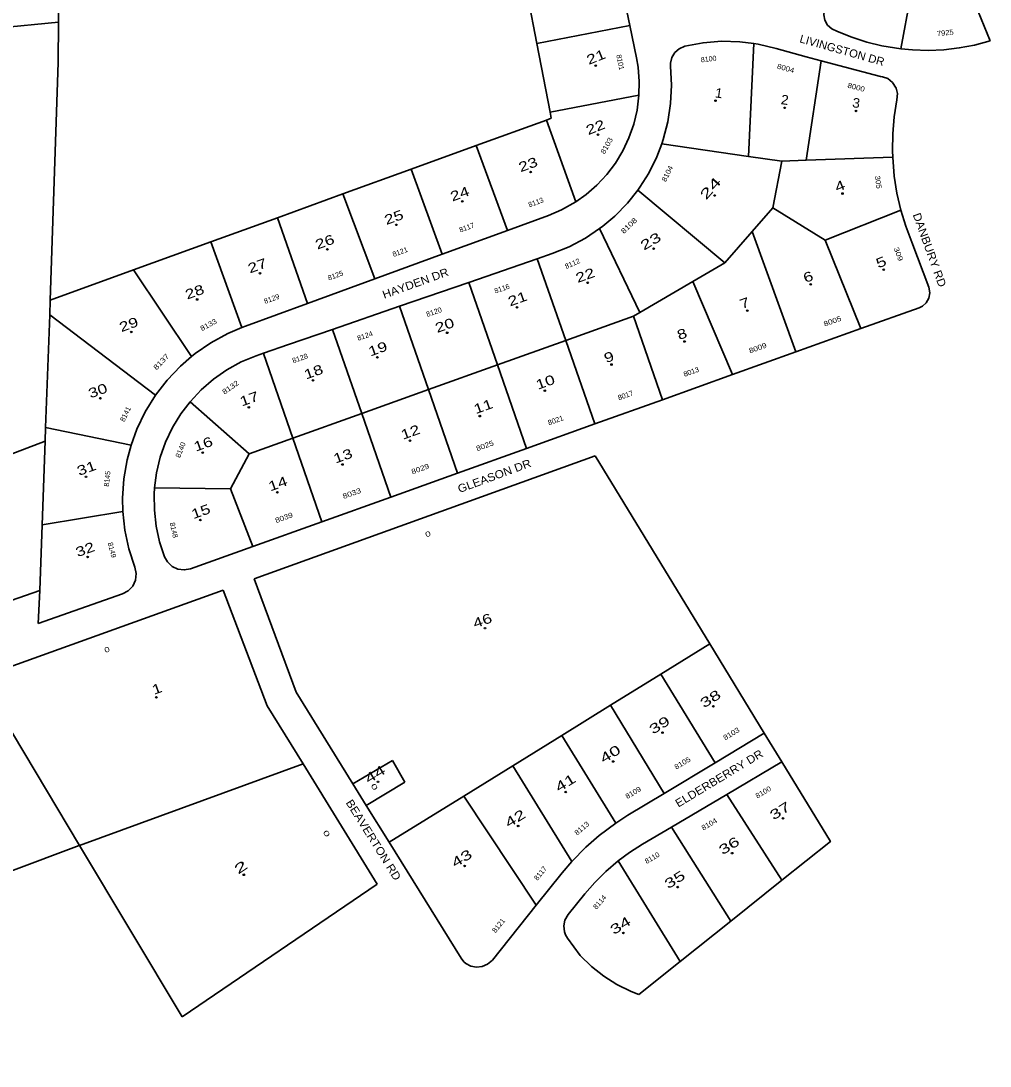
# Model space of a CAD drawing. Extents: x 2544898 to 2547598, y 582139 to 585083.
# Drawn here: x 2546061 to 2547574, y 582253 to 583885 of the extents above; entities that cross this region are included whole.
import ezdxf
from ezdxf.enums import TextEntityAlignment as Align

# ---------------------------------------------------------------- set-up
doc = ezdxf.new("R2010")
doc.units = 0
doc.header["$LTSCALE"] = 5
doc.header["$PDMODE"] = 32
doc.header["$PDSIZE"] = 2.5
for name, color, linetype in [('20', 7, 'Continuous'), ('38', 7, 'Continuous'), ('39', 7, 'Continuous'), ('41', 7, 'Continuous')]:
    doc.layers.add(name, color=color, linetype=linetype)
doc.layers.add('40', color=7, linetype='Continuous', lineweight=35)

msp = doc.modelspace()

# ---------------------------------------------------------------- linework, layer by layer
at = {"layer": '40'}
for p, q in [((2547517.332, 583993.722), (2547574.061, 583853.744)), ((2546990.285, 583981.663), (2547011.559, 583878.034)), ((2547458.782, 583972.936), (2547434.725, 583841.385)), ((2546846.633, 583951.919), (2546866.389, 583849.508)), ((2546119.727, 583883.075), (2546008.192, 583872.182)), ((2546866.389, 583849.508), (2547011.559, 583878.034)), ((2547011.559, 583878.034), (2547021.921, 583827.561)), ((2546866.389, 583849.508), (2546887.023, 583742.555)), ((2547205.315, 583849.894), (2547196.906, 583673.561)), ((2547286.961, 583828.952), (2547239.863, 583842.11)), ((2547286.963, 583828.951), (2547286.961, 583828.952)), ((2547310.333, 583822.802), (2547286.963, 583828.951)), ((2547310.333, 583822.802), (2547286.724, 583667.397)), ((2547402.839, 583798.46), (2547310.333, 583822.802)), ((2546887.023, 583742.555), (2547025.781, 583768.902)), ((2546887.023, 583742.555), (2546888.871, 583732.974)), ((2547196.906, 583673.561), (2547061.6, 583692.968)), ((2547249.091, 583666.076), (2547196.906, 583673.561)), ((2547235.069, 583593.299), (2547249.091, 583666.076)), ((2547249.091, 583666.076), (2547286.724, 583667.397)), ((2547286.724, 583667.397), (2547422.112, 583672.147)), ((2547159.702, 583507.497), (2547023.972, 583620.599)), ((2546563.772, 583614.931), (2546461.373, 583577.75)), ((2547202.606, 583556.341), (2547235.069, 583593.299)), ((2547235.069, 583593.299), (2547316.352, 583542.79)), ((2547316.352, 583542.79), (2547434.806, 583589.59)), ((2546461.373, 583577.75), (2546508.568, 583443.889)), ((2546884.468, 583581.244), (2546820.501, 583557.87)), ((2546820.501, 583557.87), (2546718.533, 583520.611)), ((2546964.536, 583560.657), (2547027.514, 583429.68)), ((2547159.702, 583507.497), (2547202.606, 583556.341)), ((2547202.606, 583556.341), (2547270.932, 583368.212)), ((2546357.446, 583540.015), (2546236.82, 583496.216)), ((2547316.352, 583542.79), (2547372.38, 583404.561)), ((2547478.302, 583469.476), (2547451.897, 583539.755)), ((2546718.533, 583520.611), (2546613.763, 583482.328)), ((2546867.172, 583513.676), (2546890.599, 583521.755)), ((2546760.3, 583476.821), (2546867.172, 583513.676)), ((2546867.172, 583513.676), (2546911.569, 583385.934)), ((2547110.206, 583478.359), (2547159.702, 583507.497)), ((2546236.82, 583496.216), (2546327.202, 583360.932)), ((2546613.763, 583482.328), (2546508.568, 583443.889)), ((2546652.082, 583439.501), (2546760.3, 583476.821)), ((2546760.3, 583476.821), (2546805.11, 583347.891)), ((2547027.514, 583429.68), (2547110.206, 583478.359)), ((2547110.206, 583478.359), (2547172.15, 583332.817)), ((2546105.966, 583426.325), (2546106.732, 583448.981)), ((2546508.568, 583443.889), (2546411.864, 583408.547)), ((2546547.575, 583403.461), (2546652.082, 583439.501)), ((2546652.082, 583439.501), (2546697.31, 583309.368)), ((2547463.332, 583437.149), (2547372.38, 583404.561)), ((2546271.128, 583300.49), (2546105.966, 583426.325)), ((2546911.569, 583385.934), (2547017.518, 583423.795)), ((2547017.518, 583423.795), (2547027.514, 583429.68)), ((2547017.518, 583423.795), (2547062.759, 583293.623)), ((2546411.864, 583408.547), (2546406.068, 583406.361)), ((2546478.758, 583379.729), (2546547.575, 583403.461)), ((2546547.575, 583403.461), (2546593.207, 583272.167)), ((2547372.38, 583404.561), (2547270.932, 583368.212)), ((2546805.11, 583347.891), (2546911.569, 583385.934)), ((2546911.569, 583385.934), (2546956.841, 583255.672)), ((2547270.932, 583368.212), (2547172.15, 583332.817)), ((2546697.31, 583309.368), (2546805.11, 583347.891)), ((2546805.11, 583347.891), (2546850.414, 583217.539)), ((2547172.15, 583332.817), (2547062.759, 583293.623)), ((2546593.207, 583272.167), (2546697.31, 583309.368)), ((2546697.31, 583309.368), (2546742.646, 583178.924)), ((2546325.207, 583290.399), (2546325.133, 583290.313)), ((2546417.321, 583209.314), (2546325.207, 583290.399)), ((2547062.759, 583293.623), (2546956.841, 583255.672)), ((2546485.587, 583233.709), (2546593.207, 583272.167)), ((2546593.207, 583272.167), (2546638.573, 583141.635)), ((2546233.13, 583222.689), (2546099.594, 583249.983)), ((2546956.841, 583255.672), (2546850.414, 583217.539)), ((2545796.27, 583114.276), (2546098.826, 583228.71)), ((2546417.321, 583209.314), (2546485.587, 583233.709)), ((2546485.587, 583233.709), (2546530.985, 583103.085)), ((2546388.446, 583154.645), (2546417.321, 583209.314)), ((2546850.414, 583217.539), (2546742.646, 583178.924)), ((2546957.583, 583205.715), (2546425.396, 583013.694)), ((2546957.583, 583205.715), (2547136.42, 582912.411)), ((2546742.646, 583178.924), (2546638.573, 583141.635)), ((2546388.091, 583154.649), (2546269.785, 583156.096)), ((2546388.091, 583154.649), (2546423.236, 583064.479)), ((2546388.446, 583154.645), (2546388.091, 583154.649)), ((2546638.573, 583141.635), (2546530.985, 583103.085)), ((2546220.251, 583118.975), (2546094.104, 583098.016)), ((2546530.985, 583103.085), (2546423.268, 583064.491)), ((2546423.236, 583064.479), (2546325.625, 583029.543)), ((2546423.268, 583064.491), (2546423.236, 583064.479)), ((2546425.396, 583013.694), (2546490.736, 582836.753)), ((2546016.803, 582969.9), (2546090.403, 582995.582)), ((2546090.403, 582995.582), (2546087.806, 582944.09)), ((2546445.723, 582815.713), (2546376.823, 582996.041)), ((2546087.806, 582944.09), (2546219.684, 582990.386)), ((2547136.42, 582912.411), (2547221.578, 582772.746)), ((2546981.47, 582816.504), (2547060.146, 582865.201)), ((2546490.736, 582836.753), (2546579.44, 582693.673)), ((2546501.803, 582725.265), (2546445.723, 582815.713)), ((2546905.587, 582769.535), (2546981.47, 582816.504)), ((2547065.314, 582678.798), (2546981.47, 582816.504)), ((2546829.008, 582722.135), (2546905.587, 582769.535)), ((2546989.705, 582632.511), (2546905.587, 582769.535)), ((2547144.853, 582726.617), (2547221.578, 582772.746)), ((2547221.578, 582772.746), (2547248.82, 582728.069)), ((2546617.254, 582537.079), (2546501.803, 582725.265)), ((2546579.44, 582693.673), (2546640.889, 582730.104)), ((2546640.889, 582730.104), (2546660.223, 582696.65)), ((2546752.455, 582674.751), (2546829.008, 582722.135)), ((2546921.162, 582572.727), (2546829.008, 582722.135)), ((2547065.314, 582678.798), (2547144.853, 582726.617)), ((2547248.82, 582728.069), (2547163.151, 582677.402)), ((2546579.44, 582693.673), (2546600.266, 582660.08)), ((2546635.897, 582602.606), (2546752.455, 582674.751)), ((2546865.403, 582504.227), (2546752.455, 582674.751)), ((2547008.636, 582644.723), (2547065.314, 582678.798)), ((2547163.151, 582677.402), (2547076.535, 582626.174)), ((2547248.986, 582543.241), (2547163.151, 582677.402)), ((2546989.705, 582632.511), (2547008.636, 582644.723)), ((2547076.535, 582626.174), (2547031.377, 582599.466)), ((2547169.217, 582479.52), (2547076.535, 582626.174)), ((2546152.65, 582597.539), (2546312.953, 582329.813)), ((2546635.897, 582602.606), (2546748.095, 582421.628)), ((2546905.777, 582554.722), (2546921.162, 582572.727)), ((2547090.008, 582416.247), (2546993.55, 582573.427)), ((2546865.403, 582504.227), (2546905.777, 582554.722)), ((2547248.986, 582543.241), (2547169.217, 582479.52)), ((2546312.953, 582329.813), (2546617.254, 582537.079)), ((2546941.329, 582521.848), (2546915.13, 582489.586)), ((2546797.023, 582418.702), (2546865.403, 582504.227)), ((2547169.217, 582479.52), (2547090.008, 582416.247)), ((2546914.213, 582452.949), (2546934.022, 582425.899)), ((2547090.008, 582416.247), (2547025.538, 582364.748)), ((2547025.538, 582364.748), (2547013.608, 582369.379))]:
    msp.add_line(p, q, dxfattribs=at)
for points in [[(2546236.82, 583496.216), (2546106.732, 583448.981), (2546119.277, 583819.984), (2546119.727, 583883.075), (2546120.935, 584052.349), (2546121.565, 584140.681), (2546122.43, 584261.873)], [(2547315.538, 583904.365), (2547314.358, 583894.697), (2547316.148, 583886.108), (2547320.474, 583878.474), (2547326.921, 583872.522), (2547335.821, 583868.565)], [(2547335.821, 583868.565), (2547358.347, 583859.463), (2547381.464, 583851.987), (2547405.055, 583846.176), (2547434.725, 583841.385)], [(2547097.609, 583845.444), (2547088.43, 583841.474), (2547081.696, 583835.491), (2547077.042, 583827.778), (2547074.887, 583819.03), (2547074.912, 583814.263)], [(2547205.315, 583849.894), (2547183.335, 583852.512), (2547154.563, 583853.186), (2547125.881, 583850.822), (2547097.609, 583845.444)], [(2547239.863, 583842.11), (2547211.873, 583848.806), (2547205.315, 583849.894)], [(2547434.725, 583841.385), (2547453.176, 583839.655), (2547477.463, 583838.979), (2547501.736, 583840.034), (2547525.873, 583842.814), (2547549.75, 583847.304), (2547574.061, 583853.744)], [(2547025.781, 583768.902), (2547026.243, 583790.375), (2547024.424, 583812.781), (2547021.921, 583827.561)], [(2547061.6, 583692.968), (2547063.888, 583699.823), (2547071.054, 583727.536), (2547075.31, 583755.842), (2547076.612, 583784.436), (2547074.912, 583814.263)], [(2547428.619, 583761.64), (2547429.365, 583771.547), (2547427.214, 583780.232), (2547421.932, 583788.646), (2547414.179, 583794.858), (2547405.839, 583797.875), (2547402.839, 583798.46)], [(2546927.292, 583602.565), (2546943.225, 583613.841), (2546960.202, 583628.575), (2546975.557, 583644.993), (2546989.122, 583662.918), (2547000.751, 583682.155), (2547010.317, 583702.498), (2547017.718, 583723.724), (2547022.872, 583745.605), (2547025.781, 583768.902)], [(2547422.112, 583672.147), (2547421.759, 583682.186), (2547422.206, 583708.808), (2547424.496, 583735.335), (2547428.619, 583761.64)], [(2546881.367, 583730.249), (2546771.838, 583690.479), (2546820.501, 583557.87)], [(2546888.871, 583732.974), (2546881.367, 583730.249), (2546927.292, 583602.565)], [(2546771.838, 583690.479), (2546670.304, 583653.612), (2546718.533, 583520.611)], [(2547023.972, 583620.599), (2547027.518, 583625.599), (2547041.17, 583647.359), (2547053.892, 583673.001), (2547061.6, 583692.968)], [(2547434.806, 583589.59), (2547428.697, 583616.055), (2547424.546, 583642.354), (2547422.112, 583672.147)], [(2546670.304, 583653.612), (2546563.772, 583614.931), (2546613.763, 583482.328)], [(2546964.536, 583560.657), (2546969.536, 583564.455), (2546988.168, 583580.187), (2547008.131, 583600.701), (2547023.972, 583620.599)], [(2546884.468, 583581.244), (2546905.151, 583590.047), (2546927.292, 583602.565)], [(2547451.897, 583539.755), (2547442.405, 583564.631), (2547434.806, 583589.59)], [(2546461.373, 583577.75), (2546357.446, 583540.015), (2546406.068, 583406.361)], [(2546890.599, 583521.755), (2546917.139, 583532.477), (2546942.426, 583545.891), (2546964.536, 583560.657)], [(2547463.332, 583437.149), (2547468.332, 583439.601), (2547474.441, 583445.091), (2547478.456, 583452.312), (2547479.898, 583460.447), (2547478.302, 583469.476)], [(2546098.826, 583228.71), (2546099.594, 583249.983), (2546105.966, 583426.325)], [(2546406.068, 583406.361), (2546384.171, 583396.991), (2546357.743, 583382.583), (2546332.955, 583365.513), (2546327.202, 583360.932)], [(2546428.491, 583362.286), (2546439.564, 583366.129), (2546478.758, 583379.729)], [(2546327.202, 583360.932), (2546310.071, 583345.961), (2546289.339, 583324.141), (2546271.128, 583300.49)], [(2546325.207, 583290.399), (2546342.448, 583309.012), (2546361.674, 583325.74), (2546382.588, 583340.304), (2546404.946, 583352.533), (2546428.491, 583362.286)], [(2546439.564, 583366.129), (2546439.634, 583365.927), (2546485.587, 583233.709)], [(2546271.128, 583300.49), (2546255.202, 583274.658), (2546242.166, 583247.53), (2546233.13, 583222.689)], [(2546325.133, 583290.313), (2546310.759, 583271.369), (2546297.741, 583249.983), (2546287.017, 583227.36), (2546278.704, 583203.744), (2546272.89, 583179.392), (2546269.785, 583156.096)], [(2546090.403, 582995.582), (2546094.104, 583098.016), (2546098.826, 583228.71)], [(2546233.13, 583222.689), (2546226.904, 583199.785), (2546221.788, 583170.125), (2546219.778, 583140.094), (2546220.251, 583118.975)], [(2546269.785, 583156.096), (2546269.132, 583146.234), (2546269.347, 583121.199), (2546272.165, 583096.322), (2546277.552, 583071.872), (2546285.453, 583048.115)], [(2546220.251, 583118.975), (2546223.372, 583090.099), (2546229.657, 583060.663), (2546238.962, 583032.04)], [(2546325.625, 583029.543), (2546316.168, 583027.793), (2546306.202, 583029.086), (2546297.129, 583033.406), (2546289.843, 583040.326), (2546285.453, 583048.115)], [(2546219.684, 582990.386), (2546228.641, 582995.251), (2546235.614, 583002.686), (2546239.895, 583011.936), (2546241.05, 583022.063), (2546238.962, 583032.04)], [(2546376.823, 582996.041), (2545995.927, 582859.287), (2546152.65, 582597.539)], [(2547144.853, 582726.617), (2547060.146, 582865.201), (2547136.42, 582912.411)], [(2546151.992, 582597.298), (2546152.65, 582597.539), (2546501.803, 582725.265)], [(2547248.82, 582728.069), (2547324.659, 582603.689), (2547248.986, 582543.241)], [(2546660.223, 582696.65), (2546600.266, 582660.08), (2546635.897, 582602.606)], [(2546921.162, 582572.727), (2546943.025, 582595.07), (2546963.7, 582613.161), (2546989.705, 582632.511)], [(2546151.992, 582597.298), (2545413.122, 582320.217), (2545425.191, 582253.127)], [(2546993.55, 582573.427), (2547011.253, 582586.58), (2547031.377, 582599.466)], [(2546941.329, 582521.848), (2546957.042, 582539.852), (2546973.991, 582556.698), (2546993.55, 582573.427)], [(2546915.13, 582489.586), (2546910.186, 582480.822), (2546908.444, 582471.928), (2546909.436, 582462.92), (2546911.147, 582458.17), (2546914.213, 582452.949)], [(2546934.022, 582425.899), (2546951.581, 582408.71), (2546970.842, 582393.452), (2546991.593, 582380.294), (2547013.608, 582369.379)], [(2546748.095, 582421.628), (2546752.473, 582416.129), (2546755.514, 582413.496), (2546763.449, 582409.203), (2546772.303, 582407.463), (2546781.274, 582408.436), (2546789.55, 582412.032), (2546797.023, 582418.702)]]:
    msp.add_lwpolyline(points, dxfattribs=at)
at = {"layer": '41'}
for p in [(2546958.325, 583815.136), (2547145.406, 583760.47), (2547253.237, 583749.304), (2547364.736, 583744.387), (2546962.075, 583707.303), (2546856.743, 583649.054), (2547343.652, 583615.472), (2546750.161, 583603.221), (2547144.155, 583612.471), (2546647.246, 583566.637), (2546539.498, 583528.221), (2547048.74, 583529.389), (2546434.166, 583491.054), (2547408.068, 583496.557), (2546945.908, 583476.139), (2547294.069, 583473.64), (2546336.251, 583450.138), (2546835.576, 583437.722), (2547194.987, 583432.723), (2546233.419, 583399.304), (2546726.578, 583398.056), (2547097.072, 583384.473), (2546617.496, 583359.639), (2546983.074, 583348.474), (2546517.164, 583323.723), (2546878.992, 583307.64), (2546185.086, 583295.889), (2546416.832, 583281.556), (2546777.41, 583267.974), (2546668.328, 583229.557), (2546344.916, 583210.973), (2546562.996, 583192.391), (2546162.752, 583173.14), (2546461.414, 583148.974), (2546341.166, 583105.641), (2546165.252, 583048.058), (2546785.567, 582936.86), (2546272.583, 582828.81), (2547142.149, 582814.907), (2547062.613, 582773.813), (2546985.729, 582728.744), (2546618.543, 582696.929), (2546911.497, 582681.022), (2547250.846, 582639.929), (2546837.265, 582627.998), (2547171.31, 582585.58), (2546753.752, 582565.695), (2546409.08, 582551.813), (2547086.473, 582532.556), (2547001.636, 582460.974)]:
    msp.add_point(p, dxfattribs=at)

# ---------------------------------------------------------------- texts
at = {"layer": '20'}
for s, rotation, width, p in [('LIVINGSTON DR', 344.193, 1.05, (2547341.398, 583833.237)), ('DANBURY RD', 289.804, 1.1, (2547473.715, 583525.314)), ('HAYDEN DR', 19.886, 1.1, (2546679.044, 583469.507)), ('GLEASON DR', 20.249, 1.1, (2546802.317, 583168.647)), ('ELDERBERRY DR', 31.139, 1.1, (2547154.261, 582697.041)), ('BEAVERTON RD', 302.044, 1.1, (2546606.182, 582602.923))]:
    msp.add_text(s, height=12.5, rotation=rotation, dxfattribs=dict(at, width=width)).set_placement(p, align=Align.CENTER)
at = {"layer": '38'}
for s, rotation, width, p in [('21', 21.772, 1.35, (2546961.536, 583821.786)), ('1', 351.838, 1.05, (2547149.614, 583764.925)), ('2', 351.838, 1.05, (2547252.542, 583754.429)), ('3', 351.838, 1.05, (2547364.06, 583749.523)), ('22', 21.772, 1.35, (2546960.716, 583712.107)), ('23', 19.956, 1.35, (2546855.285, 583653.781)), ('24', 48.705, 1.7, (2547143.131, 583618.778)), ('4', 21.558, 1.4, (2547342.253, 583620.35)), ('24', 19.956, 1.35, (2546748.672, 583608.021)), ('25', 19.956, 1.35, (2546645.794, 583571.434)), ('26', 19.956, 1.35, (2546538.009, 583533.034)), ('23', 30.485, 1.5, (2547047.885, 583534.627)), ('27', 19.956, 1.35, (2546432.677, 583495.808)), ('5', 21.558, 1.4, (2547406.678, 583501.418)), ('22', 19.713, 1.35, (2546944.447, 583480.852)), ('6', 19.713, 1.35, (2547292.6, 583478.4)), ('28', 19.956, 1.35, (2546334.758, 583454.955)), ('21', 19.713, 1.35, (2546838.771, 583444.126)), ('7', 19.713, 1.35, (2547193.508, 583437.44)), ('29', 19.956, 1.35, (2546231.933, 583404.075)), ('20', 19.713, 1.35, (2546725.09, 583402.772)), ('8', 19.713, 1.35, (2547095.59, 583389.227)), ('19', 19.713, 1.35, (2546620.695, 583366.046)), ('9', 19.713, 1.35, (2546981.565, 583353.173)), ('18', 19.713, 1.35, (2546520.323, 583330.099)), ('10', 19.713, 1.35, (2546882.184, 583314.1)), ('30', 19.956, 1.35, (2546183.613, 583300.609)), ('17', 19.713, 1.35, (2546420.003, 583287.965)), ('11', 19.713, 1.35, (2546785.253, 583276.093)), ('12', 19.713, 1.35, (2546671.519, 583236.019)), ('16', 19.713, 1.35, (2546348.112, 583217.353)), ('13', 19.713, 1.35, (2546566.187, 583198.793)), ('31', 19.956, 1.35, (2546165.93, 583179.637)), ('14', 19.713, 1.35, (2546464.59, 583155.381)), ('15', 19.713, 1.35, (2546344.325, 583112.074)), ('32', 19.956, 1.35, (2546163.773, 583052.825)), ('46', 19.84, 1.35, (2546784.053, 582941.563)), ('1', 19.75, 1.35, (2546275.799, 582835.283)), ('38', 31.756, 1.5, (2547141.369, 582820.316)), ('39', 31.756, 1.5, (2547061.85, 582779.25)), ('40', 31.756, 1.5, (2546984.944, 582734.13)), ('44', 31.756, 1.5, (2546617.75, 582702.343)), ('41', 31.756, 1.5, (2546914.923, 582689.061)), ('37', 31.756, 1.5, (2547250.06, 582645.385)), ('42', 31.756, 1.5, (2546836.466, 582633.437)), ('36', 31.756, 1.5, (2547170.541, 582590.985)), ('43', 31.756, 1.5, (2546753, 582571.144)), ('2', 34.26, 1.8, (2546408.441, 582557.478)), ('35', 31.756, 1.5, (2547085.689, 582537.972)), ('34', 31.756, 1.5, (2547000.836, 582466.399))]:
    msp.add_text(s, height=15, rotation=rotation, dxfattribs=dict(at, width=width)).set_placement(p, align=Align.CENTER)
at = {"layer": '39'}
for s, rotation, width, p in [('7925', 5.55, 1.1, (2547504.46, 583862.457)), ('8101', 281.602, 0.85, (2546992.904, 583819.726)), ('8004', 344.391, 1.15, (2547253.877, 583807.101)), ('8000', 345.257, 1.15, (2547364.063, 583777.572)), ('8103', 60.833, 1.15, (2546979.002, 583688.204)), ('8104', 63.616, 1.1, (2547073.707, 583644.737)), ('305', 277.976, 1.15, (2547395.591, 583632.652)), ('8113', 20.072, 0.9, (2546866.372, 583598.037)), ('8117', 20.072, 0.85, (2546758.48, 583558.676)), ('8108', 43.801, 1.25, (2547013.05, 583562.434)), ('8121', 20.072, 0.9, (2546654.42, 583520.635)), ('309', 290.592, 1.25, (2547427.405, 583519.589)), ('8112', 23.983, 0.95, (2546923.64, 583502.486)), ('8125', 20.073, 1.05, (2546553.479, 583483.766)), ('8116', 19.027, 0.9, (2546813.352, 583463.323)), ('8129', 20.075, 1.05, (2546453.96, 583447.391)), ('8120', 19.027, 1.05, (2546707.191, 583426.771)), ('8133', 28.602, 1.15, (2546355.779, 583407.002)), ('8005', 19.713, 1.2, (2547329.321, 583412.455)), ('8124', 19.027, 1.05, (2546599.405, 583389.544)), ('8009', 19.713, 1.2, (2547212.682, 583370.643)), ('8137', 46.464, 1.25, (2546283.04, 583350)), ('8128', 19.027, 1.05, (2546498.073, 583354.557)), ('8013', 19.713, 1.05, (2547108.883, 583333.462)), ('8132', 34.85, 1.2, (2546390.524, 583309.638)), ('8141', 64.331, 0.95, (2546227.883, 583269.389)), ('8021', 19.713, 1.05, (2546897.095, 583257.652)), ('8140', 68.616, 1.05, (2546313.952, 583213.828)), ('8025', 19.713, 1.2, (2546786.662, 583218.003)), ('8029', 19.713, 1.2, (2546685.756, 583181.843)), ('8145', 84.186, 0.95, (2546199.643, 583169.622)), ('8033', 19.713, 1.25, (2546578.931, 583143.549)), ('8039', 19.713, 1.2, (2546473.066, 583105.683)), ('0', 19.84, 1.45, (2546697.826, 583080.093)), ('0', 19.75, 1.4, (2546196.808, 582899.607)), ('8103', 31.015, 1.15, (2547172.159, 582768.695)), ('8105', 31.014, 1.15, (2547095.841, 582722.827)), ('0', 301.797, 1.75, (2546609.444, 582686.94)), ('8109', 31.015, 1.1, (2547018.935, 582676.642)), ('8100', 30.601, 1.1, (2547222.021, 582677.353)), ('8104', 30.602, 1.1, (2547137.701, 582627.434)), ('0', 301.529, 1.75, (2546534.799, 582614.119)), ('8113', 40.168, 1.1, (2546939.274, 582621.378)), ('8114', 49.905, 1.05, (2546967.703, 582506.59)), ('8121', 51.357, 1.05, (2546809.871, 582470.131))]:
    msp.add_text(s, height=8, rotation=rotation, dxfattribs=dict(at, width=width)).set_placement(p, align=Align.CENTER)
for s, rotation, p in [('8100', 6.732, (2547135.107, 583821.669)), ('8017', 19.713, (2547006.165, 583296.662)), ('8148', 282.427, (2546295.952, 583089.1)), ('8149', 284.039, (2546199.433, 583057.933)), ('8110', 30.601, (2547048.549, 582574.803)), ('8117', 51.356, (2546875.159, 582551.74))]:
    msp.add_text(s, height=8, rotation=rotation, dxfattribs=at).set_placement(p, align=Align.CENTER)

doc.saveas('drawing.dxf')
